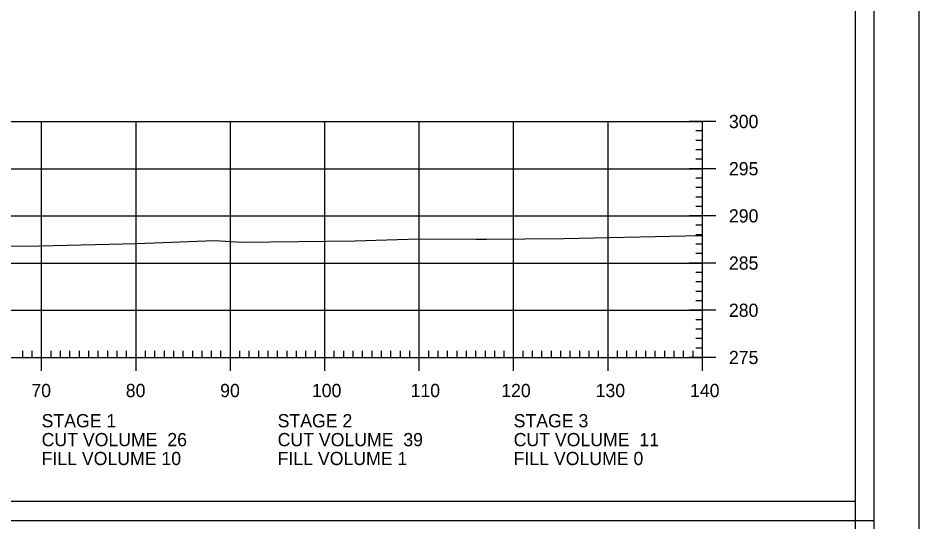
# Model space of a CAD drawing. Extents: x 1368713 to 1370673, y 380279 to 380950.
# Drawn here: x 1370577.1 to 1370672.6, y 380843.7 to 380897.1 of the extents above; entities that cross this region are included whole.
import ezdxf

# ---------------------------------------------------------------- set-up
doc = ezdxf.new("R2010")
doc.units = 0
for name, color, linetype in [('R_Axis', 7, 'Continuous'), ('R_Axis Annot', 7, 'Continuous'), ('R_Border', 7, 'Continuous'), ('R_Border Plan-Plan', 7, 'Continuous'), ('R_Exist Surface', 7, 'Continuous'), ('R_Grid', 7, 'Continuous'), ('R_No Plot', 7, 'Continuous')]:
    doc.layers.add(name, color=color, linetype=linetype)

msp = doc.modelspace()

# ---------------------------------------------------------------- linework, layer by layer
at = {"layer": 'R_Axis'}
for p, q in [((1370651.029, 380886.092), (1370648.229, 380886.092)), ((1370649.629, 380861.092), (1370649.629, 380886.092)), ((1370649.629, 380885.092), (1370648.929, 380885.092)), ((1370649.629, 380884.092), (1370648.929, 380884.092)), ((1370649.629, 380883.092), (1370648.929, 380883.092)), ((1370649.629, 380882.092), (1370648.929, 380882.092)), ((1370651.029, 380881.092), (1370648.229, 380881.092)), ((1370649.629, 380880.092), (1370648.929, 380880.092)), ((1370649.629, 380879.092), (1370648.929, 380879.092)), ((1370649.629, 380878.092), (1370648.929, 380878.092)), ((1370649.629, 380877.092), (1370648.929, 380877.092)), ((1370651.029, 380876.092), (1370648.229, 380876.092)), ((1370649.629, 380875.092), (1370648.929, 380875.092)), ((1370649.629, 380874.092), (1370648.929, 380874.092)), ((1370649.629, 380873.092), (1370648.929, 380873.092)), ((1370649.629, 380872.092), (1370648.929, 380872.092)), ((1370651.029, 380871.092), (1370648.229, 380871.092)), ((1370649.629, 380870.092), (1370648.929, 380870.092)), ((1370649.629, 380869.092), (1370648.929, 380869.092)), ((1370649.629, 380868.092), (1370648.929, 380868.092)), ((1370649.629, 380867.092), (1370648.929, 380867.092)), ((1370651.029, 380866.092), (1370648.229, 380866.092)), ((1370649.629, 380865.092), (1370648.929, 380865.092)), ((1370649.629, 380864.092), (1370648.929, 380864.092)), ((1370649.629, 380863.092), (1370648.929, 380863.092)), ((1370577.629, 380861.092), (1370577.629, 380861.792)), ((1370578.629, 380861.092), (1370578.629, 380861.792)), ((1370579.629, 380859.692), (1370579.629, 380862.492)), ((1370580.629, 380861.092), (1370580.629, 380861.792)), ((1370581.629, 380861.092), (1370581.629, 380861.792)), ((1370582.629, 380861.092), (1370582.629, 380861.792)), ((1370583.629, 380861.092), (1370583.629, 380861.792)), ((1370584.629, 380861.092), (1370584.629, 380861.792)), ((1370585.629, 380861.092), (1370585.629, 380861.792)), ((1370586.629, 380861.092), (1370586.629, 380861.792)), ((1370587.629, 380861.092), (1370587.629, 380861.792)), ((1370588.629, 380861.092), (1370588.629, 380861.792)), ((1370589.629, 380859.692), (1370589.629, 380862.492)), ((1370590.629, 380861.092), (1370590.629, 380861.792)), ((1370591.629, 380861.092), (1370591.629, 380861.792)), ((1370592.629, 380861.092), (1370592.629, 380861.792)), ((1370593.629, 380861.092), (1370593.629, 380861.792)), ((1370594.629, 380861.092), (1370594.629, 380861.792)), ((1370595.629, 380861.092), (1370595.629, 380861.792)), ((1370596.629, 380861.092), (1370596.629, 380861.792)), ((1370597.629, 380861.092), (1370597.629, 380861.792)), ((1370598.629, 380861.092), (1370598.629, 380861.792)), ((1370599.629, 380859.692), (1370599.629, 380862.492)), ((1370600.629, 380861.092), (1370600.629, 380861.792)), ((1370601.629, 380861.092), (1370601.629, 380861.792)), ((1370602.629, 380861.092), (1370602.629, 380861.792)), ((1370603.629, 380861.092), (1370603.629, 380861.792)), ((1370604.629, 380861.092), (1370604.629, 380861.792)), ((1370605.629, 380861.092), (1370605.629, 380861.792)), ((1370606.629, 380861.092), (1370606.629, 380861.792)), ((1370607.629, 380861.092), (1370607.629, 380861.792)), ((1370608.629, 380861.092), (1370608.629, 380861.792)), ((1370609.629, 380859.692), (1370609.629, 380862.492)), ((1370610.629, 380861.092), (1370610.629, 380861.792)), ((1370611.629, 380861.092), (1370611.629, 380861.792)), ((1370612.629, 380861.092), (1370612.629, 380861.792)), ((1370613.629, 380861.092), (1370613.629, 380861.792)), ((1370614.629, 380861.092), (1370614.629, 380861.792)), ((1370615.629, 380861.092), (1370615.629, 380861.792)), ((1370616.629, 380861.092), (1370616.629, 380861.792)), ((1370617.629, 380861.092), (1370617.629, 380861.792)), ((1370618.629, 380861.092), (1370618.629, 380861.792)), ((1370619.629, 380859.692), (1370619.629, 380862.492)), ((1370620.629, 380861.092), (1370620.629, 380861.792)), ((1370621.629, 380861.092), (1370621.629, 380861.792)), ((1370622.629, 380861.092), (1370622.629, 380861.792)), ((1370623.629, 380861.092), (1370623.629, 380861.792)), ((1370624.629, 380861.092), (1370624.629, 380861.792)), ((1370625.629, 380861.092), (1370625.629, 380861.792)), ((1370626.629, 380861.092), (1370626.629, 380861.792)), ((1370627.629, 380861.092), (1370627.629, 380861.792)), ((1370628.629, 380861.092), (1370628.629, 380861.792)), ((1370629.629, 380859.692), (1370629.629, 380862.492)), ((1370630.629, 380861.092), (1370630.629, 380861.792)), ((1370631.629, 380861.092), (1370631.629, 380861.792)), ((1370632.629, 380861.092), (1370632.629, 380861.792)), ((1370633.629, 380861.092), (1370633.629, 380861.792)), ((1370634.629, 380861.092), (1370634.629, 380861.792)), ((1370635.629, 380861.092), (1370635.629, 380861.792)), ((1370636.629, 380861.092), (1370636.629, 380861.792)), ((1370637.629, 380861.092), (1370637.629, 380861.792)), ((1370638.629, 380861.092), (1370638.629, 380861.792)), ((1370639.629, 380859.692), (1370639.629, 380862.492)), ((1370640.629, 380861.092), (1370640.629, 380861.792)), ((1370641.629, 380861.092), (1370641.629, 380861.792)), ((1370642.629, 380861.092), (1370642.629, 380861.792)), ((1370643.629, 380861.092), (1370643.629, 380861.792)), ((1370644.629, 380861.092), (1370644.629, 380861.792)), ((1370645.629, 380861.092), (1370645.629, 380861.792)), ((1370646.629, 380861.092), (1370646.629, 380861.792)), ((1370647.629, 380861.092), (1370647.629, 380861.792)), ((1370648.629, 380861.092), (1370648.629, 380861.792)), ((1370649.629, 380862.092), (1370648.929, 380862.092)), ((1370649.629, 380859.692), (1370649.629, 380862.492)), ((1370369.629, 380861.092), (1370649.629, 380861.092)), ((1370651.029, 380861.092), (1370648.229, 380861.092))]:
    msp.add_line(p, q, dxfattribs=at)
at = {"layer": 'R_Border'}
msp.add_line((1370667.809, 380741.092), (1370667.809, 380946.552), dxfattribs=at)
at = {"layer": 'R_Border Plan-Plan'}
msp.add_line((1370351.629, 380843.822), (1370667.809, 380843.822), dxfattribs=at)
at = {"layer": 'R_Exist Surface'}
msp.add_lwpolyline([(1370569.913, 380872.934), (1370577.891, 380872.88), (1370585.314, 380873.073), (1370589.715, 380873.183), (1370597.952, 380873.499), (1370600.859, 380873.303), (1370612.788, 380873.461), (1370619.59, 380873.663), (1370625.637, 380873.632), (1370626.756, 380873.633), (1370634.947, 380873.714), (1370647.824, 380873.981), (1370649.629, 380874.004)], dxfattribs=at)
at = {"layer": 'R_Grid'}
for p, q in [((1370369.629, 380886.092), (1370649.629, 380886.092)), ((1370579.629, 380861.092), (1370579.629, 380886.092)), ((1370589.629, 380861.092), (1370589.629, 380886.092)), ((1370599.629, 380861.092), (1370599.629, 380886.092)), ((1370609.629, 380861.092), (1370609.629, 380886.092)), ((1370619.629, 380861.092), (1370619.629, 380886.092)), ((1370629.629, 380861.092), (1370629.629, 380886.092)), ((1370639.629, 380861.092), (1370639.629, 380886.092)), ((1370649.629, 380861.092), (1370649.629, 380886.092)), ((1370369.629, 380881.092), (1370649.629, 380881.092)), ((1370369.629, 380876.092), (1370649.629, 380876.092)), ((1370369.629, 380871.092), (1370649.629, 380871.092)), ((1370369.629, 380866.092), (1370649.629, 380866.092)), ((1370369.629, 380861.092), (1370649.629, 380861.092))]:
    msp.add_line(p, q, dxfattribs=at)
at = {"layer": 'R_No Plot'}
for points in [[(1370339.221, 380950.446), (1370672.561, 380950.446), (1370672.561, 380737.109), (1370339.221, 380737.109)], [(1370665.809, 380845.822), (1370353.629, 380845.822), (1370353.629, 380944.552), (1370603.169, 380944.552), (1370603.169, 380934.672), (1370620.709, 380934.672), (1370644.809, 380934.672), (1370644.809, 380912.339), (1370665.809, 380912.339)], [(1370353.629, 380944.552), (1370603.169, 380944.552), (1370603.169, 380934.672), (1370620.709, 380934.672), (1370644.809, 380934.672), (1370644.809, 380912.339), (1370665.809, 380912.339), (1370665.809, 380743.092), (1370353.629, 380743.092)]]:
    msp.add_lwpolyline(points, close=True, dxfattribs=at)

# ---------------------------------------------------------------- texts
at = {"layer": 'R_Axis Annot'}
for s, p in [('300', (1370652.429, 380885.392)), ('295', (1370652.429, 380880.392)), ('290', (1370652.429, 380875.392)), ('285', (1370652.429, 380870.392)), ('280', (1370652.429, 380865.392)), ('275', (1370652.429, 380860.392)), ('70', (1370578.543, 380856.892)), ('80', (1370588.543, 380856.892)), ('90', (1370598.543, 380856.892)), ('100', (1370608.257, 380856.892)), ('110', (1370618.709, 380856.892)), ('120', (1370628.312, 380856.892)), ('130', (1370638.312, 380856.892)), ('140', (1370648.312, 380856.892)), ('STAGE 1', (1370579.629, 380853.692)), ('STAGE 2', (1370604.629, 380853.692)), ('STAGE 3', (1370629.629, 380853.692)), ('CUT VOLUME  26', (1370579.629, 380851.692)), ('CUT VOLUME  39', (1370604.629, 380851.692)), ('CUT VOLUME  11', (1370629.629, 380851.692)), ('FILL VOLUME 10', (1370579.629, 380849.692)), ('FILL VOLUME 1', (1370604.629, 380849.692)), ('FILL VOLUME 0', (1370629.629, 380849.692))]:
    msp.add_text(s, height=1.4, dxfattribs=at).set_placement(p)

doc.saveas('drawing.dxf')
